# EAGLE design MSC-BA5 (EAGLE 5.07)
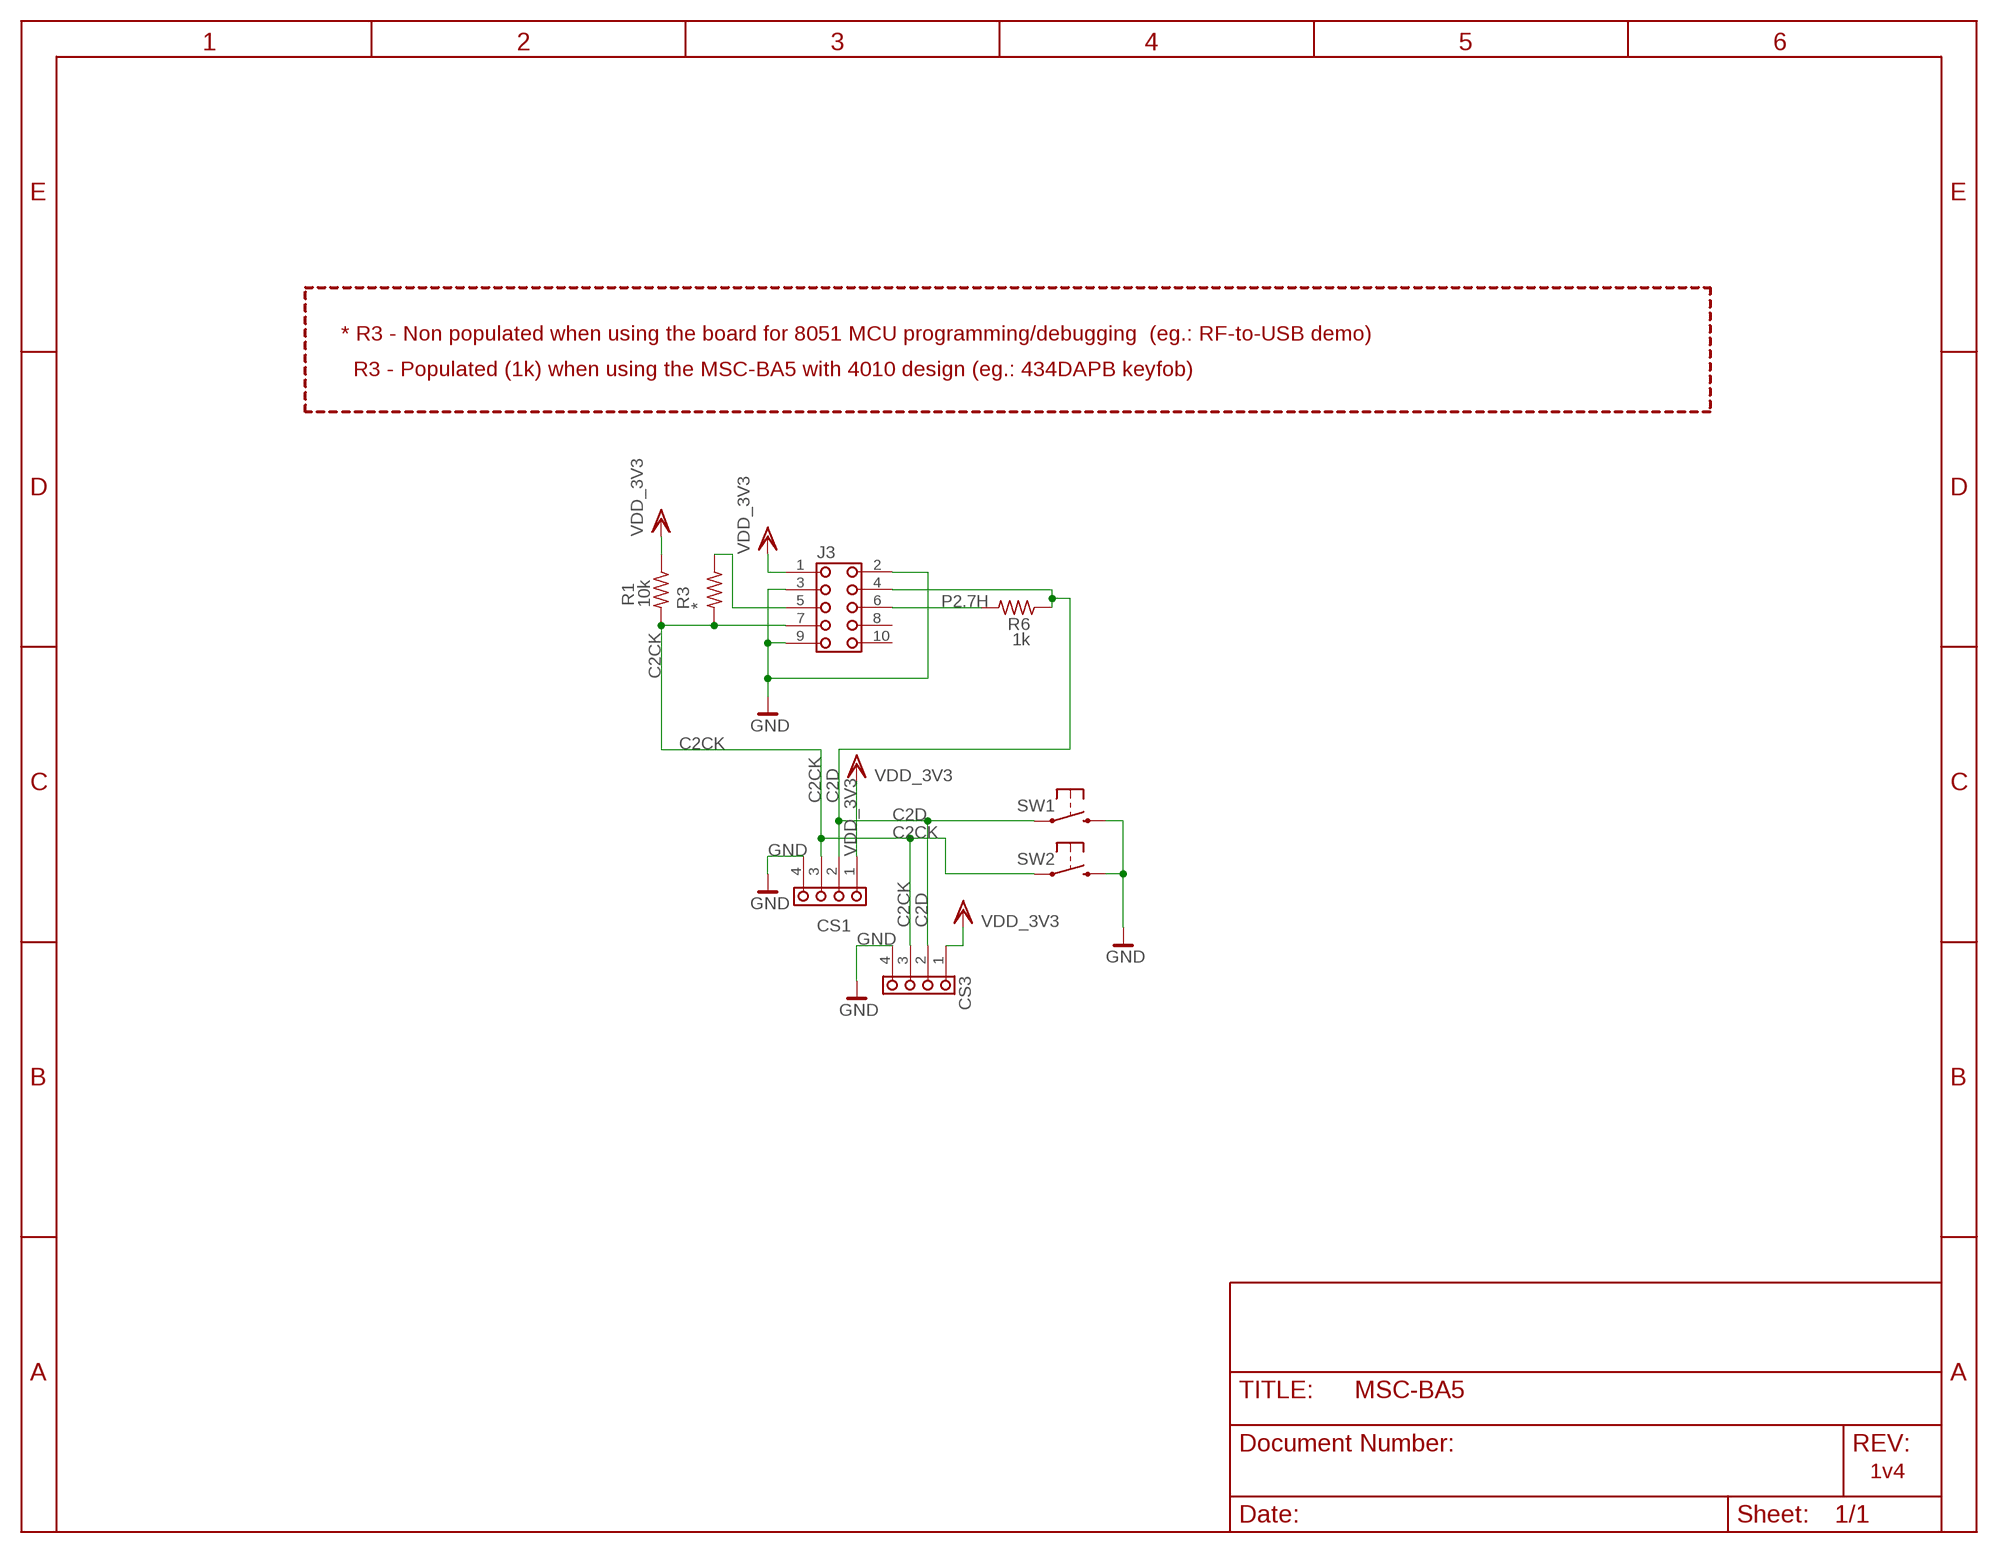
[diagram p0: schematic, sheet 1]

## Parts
CS1  90° degree, pinhead 2.54mm  PIN4  [PIN4]
CS3  90° degree, pinhead 2mm  PIN4_2MM  [PIN4S_2MM]
J3  PIN10PANDUIT  [PANDUIT-057-010-1]
R1  10k  R-US_R0603  [R0603]
R3  *  R-US_R0603  [R0603]
R6  1k  R-US_R0603  [R0603]
SW1  PUSHBUTTON1  [DTSM_32N]
SW2  PUSHBUTTON1  [DTSM_32N]

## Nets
C2CK: CS1.3 CS3.3 J3.7 R1.2 R3.2 SW2.1
C2D: CS1.2 CS3.2 J3.4 R6.1 SW1.1
GND: CS1.4 CS3.4 J3.2 J3.3 J3.9 SW1.2 SW2.2
N$2: J3.5 R3.1
P2.7H: J3.6 R6.2
VDD_3V3: CS1.1 CS3.1 J3.1 R1.1
Unconnected: J3.8 J3.10

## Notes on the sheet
- * R3 - Non populated when using the board for 8051 MCU programming/debugging  (eg.: RF-to-USB demo)
- R3 - Populated (1k) when using the MSC-BA5 with 4010 design (eg.: 434DAPB keyfob)
- 1v4

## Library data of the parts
CS1 CS3 = lve:PIN4
J3 = lve:PIN10
R1 R3 R6 = rcl:R-US_: RESISTOR, American symbol
SW1 SW2 = mgabor:PUSHBUTTON1

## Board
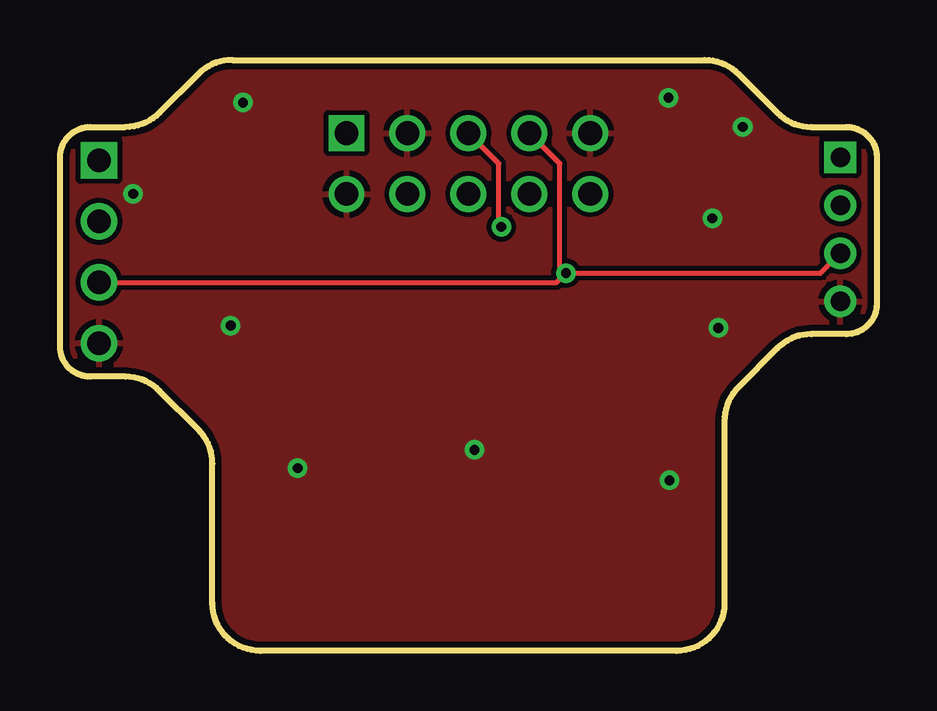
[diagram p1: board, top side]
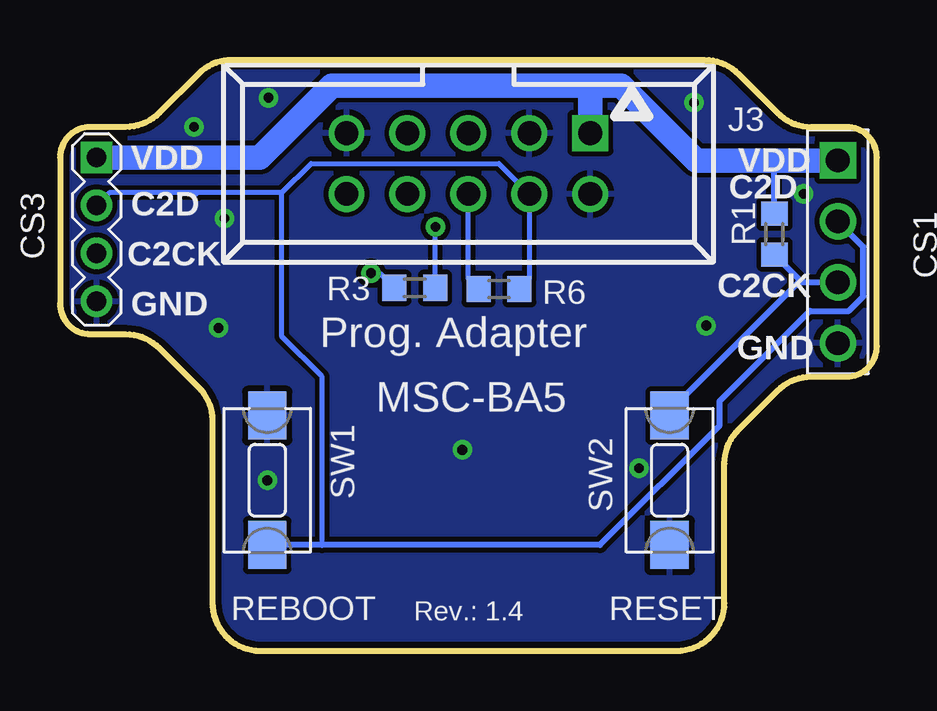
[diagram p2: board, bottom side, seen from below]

Size 34.04 x 24.64 mm. Coordinates in mm from the lower left corner, seen from the top.
Outline: 7.18,24.64 arc45 5.76,24.05 4.14,22.43 arc-45 2.73,21.84 1.27,21.84 arc90 0,20.57 0,12.7 arc90 1.27,11.43 2.73,11.43 arc-45 4.14,10.84 5.76,9.22 arc-45 6.35,7.81 6.35,2 arc90 8.35,0 25.69,0 arc90 27.69,2 27.69,9.59 arc-45 28.27,11 29.89,12.62 arc-45 31.31,13.21 32.77,13.21 arc90 34.04,14.48 34.04,20.57 arc90 32.77,21.84 31.31,21.84 arc-45 29.89,22.43 28.27,24.05 arc45 26.86,24.64 7.18,24.64
Copper layers (1*16): Top 0.035mm / dielectric 1.5mm / Bottom 0.035mm
Design rules "default *": minimum track width 10mil, minimum drill 14mil, track to track 8mil, track to pad 8mil, pad to pad 8mil, via to via 8mil, smd to smd 8mil, copper to edge 10mil, drill to drill 8mil, minimum pad ring 10mil, minimum via ring 8mil, stop-mask expansion 4mil, vias tented up to drill 0mil, thermal gap 10mil

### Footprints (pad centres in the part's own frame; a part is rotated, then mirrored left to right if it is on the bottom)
PIN4 = drill 0.991 pad 1.524 square: 1 -2.54,0 | drill 0.991 pad 1.524 round: 2 0,0; 3 2.54,0; 4 5.08,0
PIN4S_2MM = drill 0.813 pad 1.27 square: 1 0,0 | drill 0.813 pad 1.27 round: 2 2,0; 3 4,0; 4 6,0
PANDUIT-057-010-1 = drill 0.991 square: 1 -5.08,-1.27 | drill 0.991 round: 2 -5.08,1.27; 3 -2.54,-1.27; 4 -2.54,1.27; 5 0,-1.27; 6 0,1.27; 7 2.54,-1.27; 8 2.54,1.27; 9 5.08,-1.27; 10 5.08,1.27
R0603 = smd 1 x 1.1: 1 -0.85,0; 2 0.85,0
DTSM_32N = smd 2 x 1.6: 1 -2.7,0; 2 2.7,0

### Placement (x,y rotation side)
CS1  1.63,17.91 270 bottom
CS3  32.51,20.57 270 bottom
J3  17.02,20.32 180 bottom
R1  4.27,17.37 270 bottom
R3  19.25,15.14 180 bottom
R6  15.75,15.09 180 bottom
SW1  25.4,7.11 90 bottom
SW2  8.64,7.11 270 bottom

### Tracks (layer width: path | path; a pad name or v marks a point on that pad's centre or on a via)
C2CK  (via drill 0.41)
  Top 0.203: J3.7 20.83,20.32 20.83,16 v21.08,15.75 | CS1.3 20.7,15.37 v21.08,15.75 | v21.08,15.75 31.69,15.75 CS3.3
  Bottom 0.203: 20.47,15.14 R3.2 20.71,15.75 v21.08,15.75
  Bottom 0.254: SW2.1 8.64,10.01 3.28,15.37 3.11,15.37 | 4.32,16.57 R1.2 3.11,15.37 | CS1.3 3.1,15.37 3.11,15.37
C2D
  Bottom 0.203: 23.11,4.41 23.11,11.43 24.79,13.11 24.79,19.1 | 24.79,19.1 23.57,20.32 15.75,20.32 J3.4 14.48,15.51 R6.1 | 24.79,19.1 28.4,19.1 | 28.4,19.1 31.99,19.1 CS3.2 | 28.4,19.1 28.35,19.05
  Bottom 0.254: SW1.1 23.11,4.41 11.54,4.41 6.55,9.4 6.55,10.41 2.79,14.17 1.17,14.17 0.56,14.78 0.56,16.84 CS1.2
GND  (via drill 0.41)
  other vias: 7.62,22.86 25.35,23.06 28.45,21.84 27.18,18.03 27.43,13.46 3.05,19.05 7.11,13.56 9.91,7.62 25.4,7.11 17.27,8.38
  pour Bottom: 0,19.84 arc-90 2,21.84 2.73,21.84 arc45 4.14,22.43 5.76,24.05 arc-45 7.18,24.64 26.86,24.64 arc-45 28.27,24.05 29.89,22.43 arc45 31.31,21.84 32.04,21.84 arc-90 34.04,19.84 34.04,14.95 arc-90 32.04,12.95 30.48,12.95 27.69,10.16 27.69,2 arc-90 25.69,0 8.35,0 arc-90 6.35,2 6.35,7.81 arc45 5.76,9.22 4.14,10.84 arc45 2.73,11.43 2,11.43 arc-90 0,13.43
  pour Top: 0,19.84 arc-90 2,21.84 2.73,21.84 arc45 4.14,22.43 5.76,24.05 arc-45 7.18,24.64 26.86,24.64 arc-45 28.27,24.05 29.89,22.43 arc45 31.31,21.84 32.04,21.84 arc-90 34.04,19.84 34.04,14.95 arc-90 32.04,12.95 30.48,12.95 27.69,10.16 27.69,2 arc-90 25.69,0 8.35,0 arc-90 6.35,2 6.35,7.81 arc45 5.76,9.22 4.14,10.84 arc45 2.73,11.43 2,11.43 arc-90 0,13.43
N$2  (via drill 0.41)
  Top 0.203: v18.39,17.68 18.29,17.78 18.29,20.32 J3.5
  Bottom 0.203: R3.1 18.4,17.51 v18.39,17.68
P2.7H
  Bottom 0.203: J3.6 17.02,15.51 R6.2
VDD_3V3
  Bottom 0.254: R1.1 4.27,20.34 4.37,20.45
  Bottom 0.61: 4.27,20.34 4.17,20.45 3.05,20.45
  Bottom 1.016: 11.99,23.57 10.64,23.57 7.52,20.45 3.05,20.45 CS1.1 | 11.99,23.57 22.71,23.57 25.71,20.57 CS3.1 | J3.1 11.94,23.52 11.99,23.57

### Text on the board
bPlace: C2D | VDD | VDD | C2D | C2CK | C2CK | GND | Prog. Adapter | GND | MSC-BA5 | RESET | Rev.: 1.4 | REBOOT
